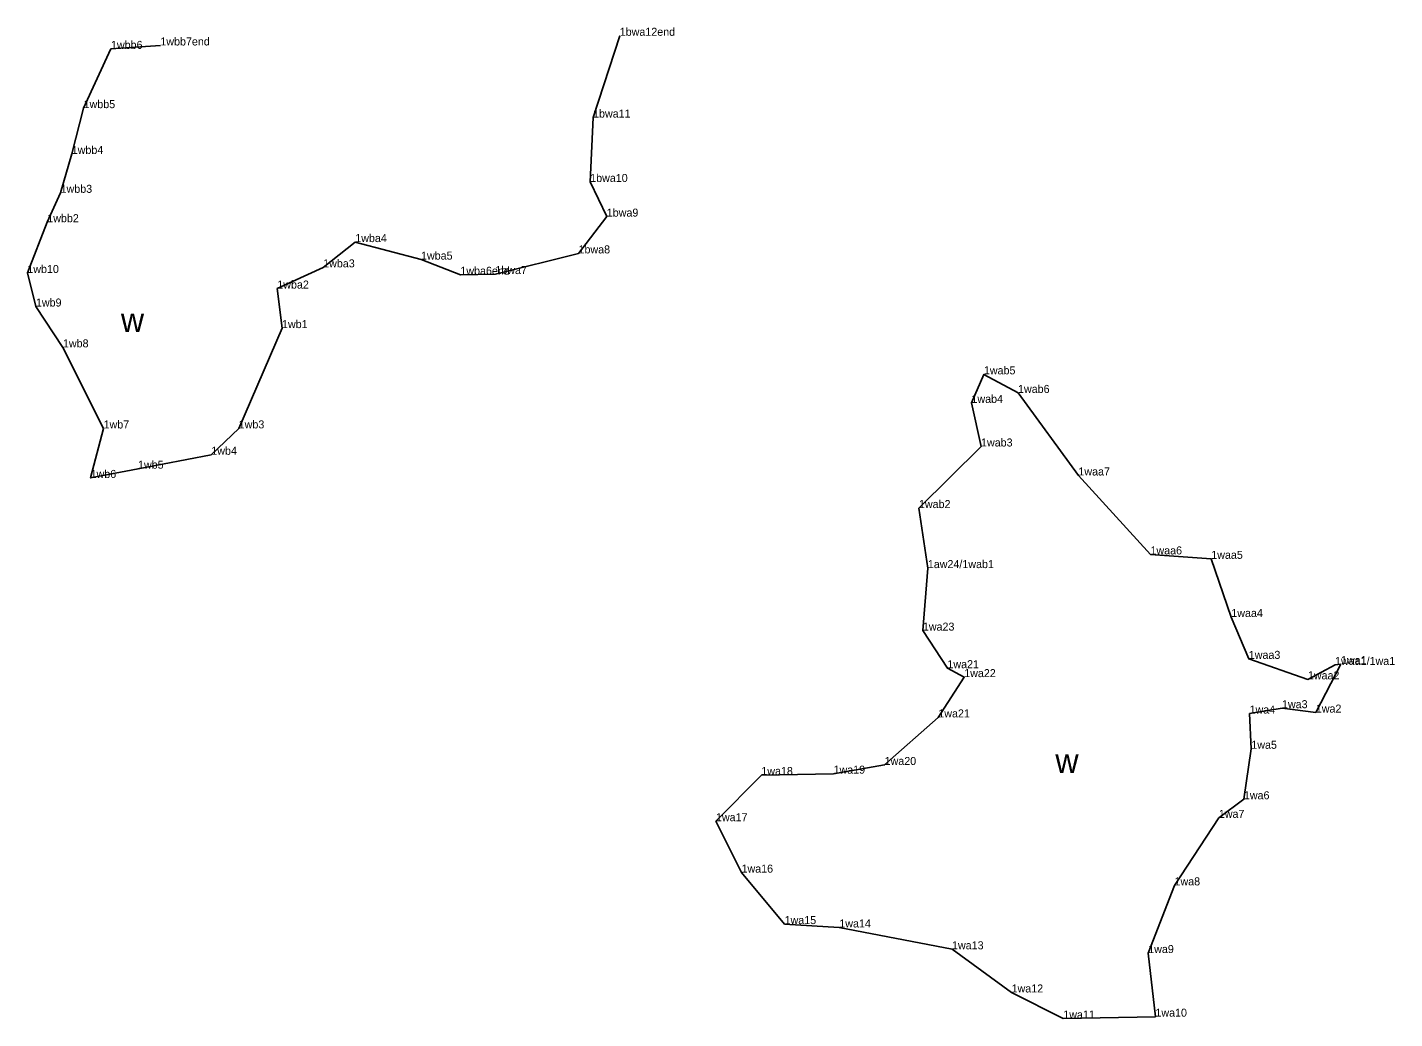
# Model space of a CAD drawing. Extents: x 2072529 to 2267990, y 436423 to 470008.
# Drawn here: x 2072529 to 2073383, y 469389 to 470008 of the extents above; entities that cross this region are included whole.
import ezdxf

# ---------------------------------------------------------------- set-up
doc = ezdxf.new("R2010")
doc.units = 0
for name, color, linetype in [('Level 3', 7, 'Continuous'), ('Old_Level_52', 7, 'Continuous'), ('Prop SS Cut Line', 7, 'Continuous')]:
    doc.layers.add(name, color=color, linetype=linetype)

msp = doc.modelspace()

# ---------------------------------------------------------------- linework, layer by layer
at = {"layer": 'Level 3'}
for p, q in [((2072898.839, 470003.302), (2072898.839, 470003.302)), ((2072581.191, 469994.992), (2072581.191, 469994.992)), ((2072612.04, 469997.123), (2072612.04, 469997.123)), ((2072564.087, 469957.983), (2072564.087, 469957.983)), ((2072882.289, 469952.109), (2072882.289, 469952.109)), ((2072556.676, 469929.393), (2072556.676, 469929.393)), ((2072880.487, 469911.886), (2072880.487, 469911.886)), ((2072549.713, 469905.113), (2072549.713, 469905.113)), ((2072541.405, 469886.751), (2072541.405, 469886.751)), ((2072890.852, 469890.243), (2072890.852, 469890.243)), ((2072733.76, 469874.345), (2072733.76, 469874.345)), ((2072873.194, 469867.269), (2072873.194, 469867.269)), ((2072713.706, 469858.547), (2072713.706, 469858.547)), ((2072774.834, 469863.39), (2072774.834, 469863.39)), ((2072528.947, 469855.037), (2072528.947, 469855.037)), ((2072799.412, 469853.957), (2072799.412, 469853.957)), ((2072821.26, 469854.358), (2072821.26, 469854.358)), ((2072685.081, 469845.318), (2072685.081, 469845.318)), ((2072534.317, 469834.092), (2072534.317, 469834.092)), ((2072688.01, 469820.635), (2072688.01, 469820.635)), ((2072551.176, 469808.58), (2072551.176, 469808.58)), ((2073126.383, 469791.746), (2073126.383, 469791.746)), ((2073147.704, 469780.128), (2073147.704, 469780.128)), ((2073147.704, 469780.128), (2073147.704, 469780.128)), ((2073147.704, 469780.128), (2073147.704, 469780.128)), ((2073118.624, 469773.918), (2073118.624, 469773.918)), ((2073118.624, 469773.918), (2073118.624, 469773.918)), ((2073118.624, 469773.918), (2073118.624, 469773.918)), ((2072576.569, 469757.944), (2072576.569, 469757.944)), ((2072660.961, 469757.987), (2072660.961, 469757.987)), ((2073124.598, 469746.696), (2073124.598, 469746.696)), ((2072643.848, 469741.521), (2072643.848, 469741.521)), ((2072598.075, 469732.839), (2072598.075, 469732.839)), ((2073185.409, 469728.576), (2073185.409, 469728.576)), ((2073185.409, 469728.576), (2073185.409, 469728.576)), ((2073185.409, 469728.576), (2073185.409, 469728.576)), ((2072568.442, 469727.055), (2072568.442, 469727.055)), ((2073085.827, 469708.232), (2073085.827, 469708.232)), ((2073085.827, 469708.232), (2073085.827, 469708.232)), ((2073085.827, 469708.232), (2073085.827, 469708.232)), ((2073230.433, 469679.28), (2073230.433, 469679.28)), ((2073091.377, 469670.751), (2073091.377, 469670.751)), ((2073268.394, 469676.526), (2073268.394, 469676.526)), ((2073268.394, 469676.526), (2073268.394, 469676.526)), ((2073268.394, 469676.526), (2073268.394, 469676.526)), ((2073280.925, 469640.192), (2073280.925, 469640.192)), ((2073088.272, 469631.703), (2073088.272, 469631.703)), ((2073291.828, 469614.071), (2073291.828, 469614.071)), ((2073291.828, 469614.071), (2073291.828, 469614.071)), ((2073291.828, 469614.071), (2073291.828, 469614.071)), ((2073345.718, 469610.244), (2073345.718, 469610.244)), ((2073349.412, 469610.76), (2073349.412, 469610.76)), ((2073103.602, 469608.231), (2073103.602, 469608.231)), ((2073114.096, 469602.66), (2073114.096, 469602.66)), ((2073328.736, 469601.262), (2073328.736, 469601.262)), ((2073312.576, 469583.259), (2073312.576, 469583.259)), ((2073097.927, 469577.501), (2073097.927, 469577.501)), ((2073292.304, 469579.898), (2073292.304, 469579.898)), ((2073333.701, 469580.507), (2073333.701, 469580.507)), ((2073293.421, 469557.904), (2073293.421, 469557.904)), ((2072987.384, 469541.531), (2072987.384, 469541.531)), ((2073032.486, 469542.355), (2073032.486, 469542.355)), ((2073064.387, 469547.795), (2073064.387, 469547.795)), ((2073288.773, 469526.361), (2073288.773, 469526.361)), ((2073273.123, 469514.779), (2073273.123, 469514.779)), ((2072959.049, 469512.683), (2072959.049, 469512.683)), ((2072975.016, 469480.557), (2072975.016, 469480.557)), ((2073245.443, 469472.592), (2073245.443, 469472.592)), ((2073001.913, 469448.422), (2073001.913, 469448.422)), ((2073036.086, 469446.318), (2073036.086, 469446.318)), ((2073106.478, 469432.674), (2073106.478, 469432.674)), ((2073229.019, 469430.339), (2073229.019, 469430.339)), ((2073143.693, 469405.734), (2073143.693, 469405.734)), ((2073175.967, 469389.444), (2073175.967, 469389.444)), ((2073233.509, 469390.609), (2073233.509, 469390.609))]:
    msp.add_line(p, q, dxfattribs=at)
at = {"layer": 'Old_Level_52'}
msp.add_line((2073333.701, 469580.507), (2073349.412, 469610.76), dxfattribs=at)
for points in [[(2072898.945, 470003.181), (2072882.289, 469952.109), (2072880.487, 469911.886), (2072890.852, 469890.243), (2072873.194, 469867.269), (2072821.26, 469854.358), (2072799.412, 469853.957)], [(2072612.04, 469997.123), (2072581.191, 469994.992), (2072564.087, 469957.983), (2072556.676, 469929.393), (2072549.713, 469905.113), (2072541.405, 469886.751), (2072528.947, 469855.037)], [(2072799.412, 469853.957), (2072774.834, 469863.39), (2072733.76, 469874.345), (2072713.706, 469858.547), (2072685.081, 469845.318), (2072688.01, 469820.635)], [(2072528.947, 469855.037), (2072534.317, 469834.092), (2072551.176, 469808.58), (2072576.569, 469757.944), (2072568.442, 469727.055), (2072598.075, 469732.839), (2072643.848, 469741.521), (2072660.961, 469757.987), (2072688.01, 469820.635)], [(2073091.377, 469670.751), (2073085.827, 469708.232), (2073124.598, 469746.696), (2073118.624, 469773.918), (2073126.383, 469791.746), (2073147.704, 469780.128), (2073185.409, 469728.576), (2073230.433, 469679.28), (2073268.394, 469676.526), (2073280.925, 469640.192), (2073291.828, 469614.071), (2073328.736, 469601.262), (2073345.718, 469610.244), (2073349.412, 469610.76)], [(2073091.377, 469670.751), (2073088.272, 469631.703), (2073103.602, 469608.231), (2073114.096, 469602.66), (2073097.927, 469577.501), (2073064.387, 469547.795), (2073032.486, 469542.355), (2072987.384, 469541.531), (2072959.049, 469512.683), (2072975.016, 469480.557), (2073001.913, 469448.422), (2073036.086, 469446.318), (2073106.478, 469432.674), (2073143.693, 469405.734), (2073175.967, 469389.444), (2073233.509, 469390.609), (2073229.019, 469430.339), (2073245.443, 469472.592), (2073273.123, 469514.779), (2073288.773, 469526.361), (2073293.421, 469557.904), (2073292.304, 469579.898), (2073312.576, 469583.259), (2073333.701, 469580.507)]]:
    msp.add_lwpolyline(points, dxfattribs=at)

# ---------------------------------------------------------------- texts
for s, p in [('1wbb7end', (2072612.04, 469997.123)), ('1bwa12end', (2072898.945, 470003.181)), ('1wbb6', (2072581.191, 469994.992)), ('1wbb5', (2072564.087, 469957.983)), ('1bwa11', (2072882.289, 469952.109)), ('1wbb4', (2072556.676, 469929.393)), ('1bwa10', (2072880.487, 469911.886)), ('1wbb3', (2072549.713, 469905.113)), ('1wbb2', (2072541.405, 469886.751)), ('1bwa9', (2072890.852, 469890.243)), ('1wba4', (2072733.76, 469874.345)), ('1wba5', (2072774.834, 469863.39)), ('1bwa8', (2072873.194, 469867.269)), ('1wb10', (2072528.947, 469855.037)), ('1wba3', (2072713.706, 469858.547)), ('1wba6end', (2072799.412, 469853.957)), ('1bwa7', (2072821.26, 469854.358)), ('1wba2', (2072685.081, 469845.318)), ('1wb9', (2072534.317, 469834.092)), ('1wb1', (2072688.01, 469820.635)), ('1wb8', (2072551.176, 469808.58)), ('1wab5', (2073126.383, 469791.746)), ('1wab6', (2073147.704, 469780.128)), ('1wab6', (2073147.704, 469780.128)), ('1wab6', (2073147.704, 469780.128)), ('1wab4', (2073118.624, 469773.918)), ('1wab4', (2073118.624, 469773.918)), ('1wab4', (2073118.624, 469773.918)), ('1wb7', (2072576.569, 469757.944)), ('1wb3', (2072660.961, 469757.987)), ('1wb4', (2072643.848, 469741.521)), ('1wab3', (2073124.598, 469746.696)), ('1wb5', (2072598.075, 469732.839)), ('1wb6', (2072568.442, 469727.055)), ('1waa7', (2073185.409, 469728.576)), ('1waa7', (2073185.409, 469728.576)), ('1waa7', (2073185.409, 469728.576)), ('1wab2', (2073085.827, 469708.232)), ('1wab2', (2073085.827, 469708.232)), ('1wab2', (2073085.827, 469708.232)), ('1waa6', (2073230.433, 469679.28)), ('1waa5', (2073268.394, 469676.526)), ('1waa5', (2073268.394, 469676.526)), ('1waa5', (2073268.394, 469676.526)), ('1aw24/1wab1', (2073091.377, 469670.751)), ('1aw24', (2073091.377, 469670.751)), ('1waa4', (2073280.925, 469640.192)), ('1wa23', (2073088.272, 469631.703)), ('1waa3', (2073291.828, 469614.071)), ('1waa3', (2073291.828, 469614.071)), ('1waa3', (2073291.828, 469614.071)), ('1wa21', (2073103.602, 469608.231)), ('1waa1/1wa1', (2073345.718, 469610.244)), ('1wa1', (2073349.412, 469610.76)), ('1wa22', (2073114.096, 469602.66)), ('1waa2', (2073328.736, 469601.262)), ('1wa4', (2073292.304, 469579.898)), ('1wa3', (2073312.576, 469583.259)), ('1wa2', (2073333.701, 469580.507)), ('1wa21', (2073097.927, 469577.501)), ('1wa5', (2073293.421, 469557.904)), ('1wa20', (2073064.387, 469547.795)), ('1wa18', (2072987.384, 469541.531)), ('1wa19', (2073032.486, 469542.355)), ('1wa6', (2073288.773, 469526.361)), ('1wa17', (2072959.049, 469512.683)), ('1wa7', (2073273.123, 469514.779)), ('1wa16', (2072975.016, 469480.557)), ('1wa8', (2073245.443, 469472.592)), ('1wa15', (2073001.913, 469448.422)), ('1wa14', (2073036.086, 469446.318)), ('1wa13', (2073106.478, 469432.674)), ('1wa9', (2073229.019, 469430.339)), ('1wa12', (2073143.693, 469405.734)), ('1wa10', (2073233.509, 469390.609)), ('1wa11', (2073175.967, 469389.444))]:
    msp.add_text(s, height=5).set_placement(p)
at = {"layer": 'Prop SS Cut Line'}
for p in [(2072587.365, 469818.225), (2073171.026, 469542.822)]:
    msp.add_text('w', height=15, dxfattribs=at).set_placement(p)

doc.saveas('drawing.dxf')
